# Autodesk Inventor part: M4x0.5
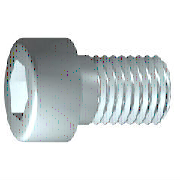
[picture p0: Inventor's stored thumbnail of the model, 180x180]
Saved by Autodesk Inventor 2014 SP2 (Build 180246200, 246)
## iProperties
IsCustomPart: 1
Company: 한국ATC센터
Created: 2014-10
Part Number: M4x0.5
Material: 강철, 연강
Description: 6각머리 태핑 나사
Document SubType Name: Modeling
Standard: KS B 1003
Designer: 한국ATC센터
Standards Organization: KS
Language: ko-KR
Size Designation: M 4 x 16
Categories: <MemberInstance><Categories><Category DisplayName="조임쇠" InternalName="e4da775c-781d-43d5-af7c-5136215cf5a6" Mnemonic="FSTN"><Category DisplayName="볼트" InternalN
Density: 7.86 g/cm^3
Mass: 2.62973 g
Surface Area: 3.81119 cm^2
Volume: 0.334572 cm^3
Appearance: 강철
Author: KYOUNG IL JANG
Revision Number: 1
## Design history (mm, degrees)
sketch "스케치1"
  geometry: L1 (-1, 0)-(16, 0); L2 (16, 0)-(16, 2); L3 (16, 2)-(1.75, 2); L4 (1.75, 2)-(1.32, 2); L5 (1.32, 2)-(0, 2); L6 (0, 2)-(0, 3.5); L7 (0, 3.5)-(-4, 3.5); L8 (-4, 3.5)-(-4, 1.732); L9 (-4, 1.732)-(-2, 1.732); L10 (-2, 1.732)-(-1, 0); L11 (-8, 0)-(20, 0) reference; L12 (0, -0.7)-(0, 4.2) reference; L13 (1.75, 2)-(0, 2)
  constraints: 22 end point, 6 parallel, 2 collinear, 2 perpendicular, 1 horizontal, 1 point on line
  dimensions: "d1" = 14.25 distance from line of L3.end L2 (= GEL); "d2" = 0.42952 distance of L4.end L3.end (computed from GAL); "d3" = 4 distance between parallel lines of L8 L6 (= KOH); "d4" = 2 distance of L8.end L9.end (= INTI); "d5" = 60 deg angle of L10 L1; "d6" = 4 diameter of L3 L1 (= GD); "d7" = 4 diameter of L5 L1 (= BDM); "d8" = 3.4641 diameter of L9 L1 (= 1.1547 x SW); "d9" = 7 diameter of L7 L1 (= KOD); "d26" = 16 distance between parallel lines of L12 L2 (= NLG)
revolve "본체" sketch "스케치1" stored, may be unused: angle "d10" = 90 deg
sketch "스케치2"
  geometry: L1 (0, -4.9)-(0, 4.9) reference; L2 (-4.9, 0)-(4.9, 0) reference; L3 (1.732, 0)-(0.866, -1.5); L4 (0.866, -1.5)-(-0.866, -1.5); L5 (-0.866, -1.5)-(-1.732, 0); L6 (-1.732, 0)-(-0.866, 1.5); L7 (-0.866, 1.5)-(0.866, 1.5); L8 (0.866, 1.5)-(1.732, 0); 2 further points
  constraints: 12 end point, 1 coincident, 1 horizontal alignment, 1 point on line, 12 other
extrude "슬롯" join sketch "스케치2" stored distance "d11" = 10; taper "d12" = 0 deg
workplane "Work Plane1"
fillet "Fillet2" dims "d30" = 0.1 (= R)
body "Solid1"
fillet "모깎기1" dims "d17" = 0.4 (= RR)
feature "스레드" dims "d13" = 14.25 (= GEL), "d14" = 0
chamfer "모따기1" distance "d15" = 0.42941 (= -0.5 x SPD + 0.5 x GD); stored, may be unused: second distance "d16" = 0.42941 (= GUL), angle "d27" = 45 deg
other parameters: "GD" = 4 (= NND) [user parameter; used in 2 equation terms], "NLG" = 16 [user parameter; used in 1 equation term], "GEL" = 14.25 [user parameter; used in 2 equation terms], "KOD" = 7 [user parameter; used in 1 equation term], "KOH" = 4 [user parameter; used in 1 equation term], "INTI" = 2 [user parameter; used in 1 equation term], "GAL" = 0.42941 (= 0.61345 x PTC) [user parameter; used in 1 equation term], "GUL" = 0.42941 (= 0.61345 x PTC) [user parameter; used in 1 equation term], "BDM" = 4 (= NND) [user parameter; used in 1 equation term], "SW" = 3 [user parameter; used in 2 equation terms], "RR" = 0.4 [user parameter; used in 1 equation term], "SPD" = 3.14117 (= NND - 1.2269 x PTC) [user parameter; used in 1 equation term], "d19" = 0, "d28" = 0, "d29" = 0, "R" = 0.1 [user parameter; used in 1 equation term], "PHH" = 0.2 [user parameter], "GD1" = 3.14117 (= THREADDIA - 1.2269 x PTC) [user parameter], "THREADDIA" = 4 [user parameter; used in 1 equation term], "FAWI" = 45 deg [user parameter], "TPU" = 14.28571 (computed from PTC) [user parameter], "PTC" = 0.7 [user parameter; used in 5 equation terms], "NND" = 4 [user parameter; used in 3 equation terms], "TOA" = 30 deg [user parameter], "E0" = 3.465 (= 1.155 x SW) [user parameter]
